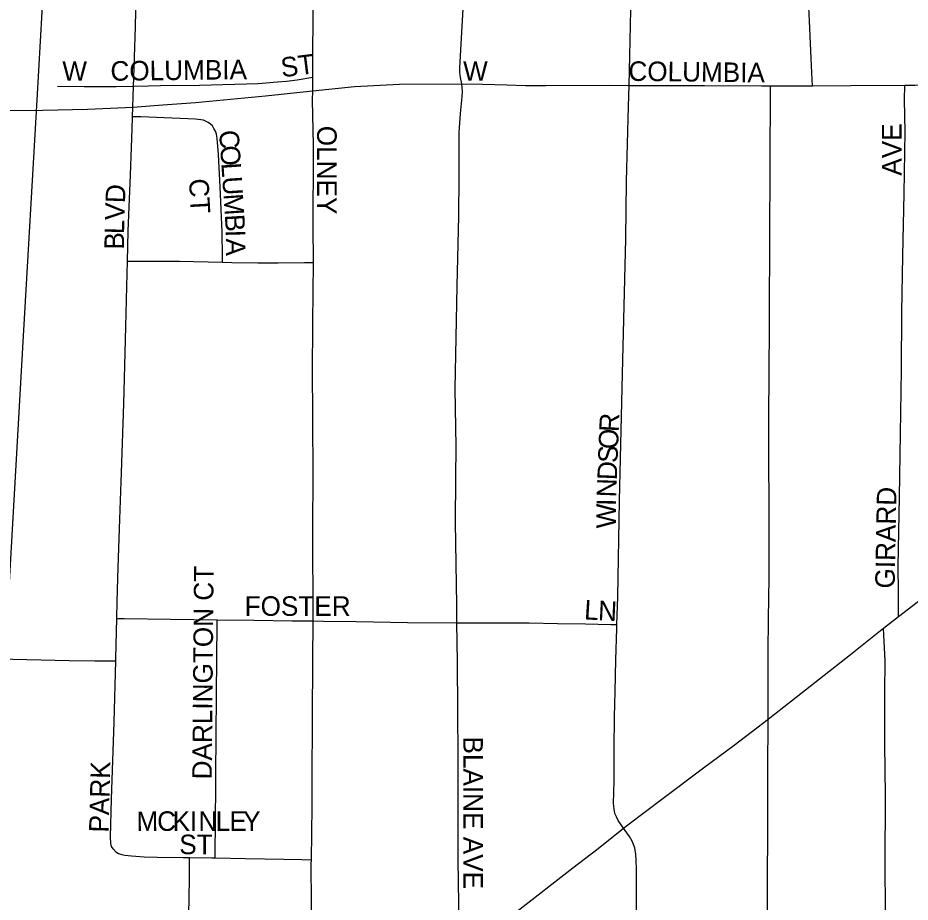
# Model space of a CAD drawing. Extents: x -97 to 34, y -21 to 22.
# Drawn here: x 5.1003 to 5.5326, y 18.9937 to 19.4221 of the extents above; entities that cross this region are included whole.
import ezdxf

# ---------------------------------------------------------------- set-up
doc = ezdxf.new("R2010")
doc.units = 0
for name, color, linetype in [('GM_X_City_Street', 7, 'Continuous'), ('GM_X_City_Street_Text', 7, 'Continuous'), ('GM_X_Rail_Line', 7, 'Continuous'), ('GM_X_State_Route', 7, 'Continuous')]:
    doc.layers.add(name, color=color, linetype=linetype)

msp = doc.modelspace()

# ---------------------------------------------------------------- linework, layer by layer
at = {"layer": 'GM_X_City_Street'}
for points in [[(5.15634, 19.38897), (5.15647, 19.39301), (5.15721, 19.41779), (5.1578, 19.44016), (5.15836, 19.45872), (5.15888, 19.47608), (5.15934, 19.49148), (5.15976, 19.50528), (5.16016, 19.52049), (5.16054, 19.53449), (5.16098, 19.55246), (5.16153, 19.56341)], [(5.24317, 19.39332), (5.24317, 19.39456), (5.24338, 19.43167), (5.24346, 19.45336), (5.24339, 19.4689), (5.24358, 19.48131), (5.24352, 19.48737), (5.24364, 19.5147), (5.24325, 19.54835), (5.24309, 19.56256)], [(5.39638, 19.38931), (5.39674, 19.40369), (5.39761, 19.44092), (5.39861, 19.48431), (5.39814, 19.52244)], [(5.48528, 19.3891), (5.48481, 19.39888), (5.48376, 19.42056), (5.48241, 19.44991)], [(5.15634, 19.38897), (5.16354, 19.38911), (5.16937, 19.38923), (5.18832, 19.38946), (5.21675, 19.39032), (5.22614, 19.39102), (5.23046, 19.3914), (5.23557, 19.39208), (5.24317, 19.39332)], [(5.24314, 19.38666), (5.24317, 19.39332)], [(5.11958, 19.38902), (5.13241, 19.38887), (5.14794, 19.38879), (5.15634, 19.38897)], [(5.1559, 19.37403), (5.15604, 19.37875), (5.15634, 19.38897)], [(5.31303, 19.12908), (5.31292, 19.13769), (5.31233, 19.17754), (5.31247, 19.19906), (5.31262, 19.21449), (5.31219, 19.24242), (5.31315, 19.29204), (5.31391, 19.32613), (5.31408, 19.34476), (5.31416, 19.36649), (5.31469, 19.37578), (5.31548, 19.3838), (5.31564, 19.38648), (5.31561, 19.38808), (5.3153, 19.39015)], [(5.3153, 19.39015), (5.32537, 19.38986), (5.33729, 19.38956), (5.34616, 19.3893), (5.35603, 19.38929), (5.38707, 19.38941), (5.39638, 19.38931)], [(5.39049, 19.12816), (5.39094, 19.1416), (5.39177, 19.1881), (5.39341, 19.25635), (5.39478, 19.31507), (5.39517, 19.3429), (5.39612, 19.37911), (5.39638, 19.38931)], [(5.39638, 19.38931), (5.40255, 19.38925), (5.41175, 19.38923), (5.42085, 19.38923), (5.43294, 19.3893), (5.4606, 19.38912), (5.46488, 19.3891)], [(5.46381, 19.0824), (5.4637, 19.09452), (5.46376, 19.11473), (5.46396, 19.13089), (5.46431, 19.15081), (5.46431, 19.1701), (5.46423, 19.18597), (5.46412, 19.20807), (5.46404, 19.22918), (5.46419, 19.24933), (5.46437, 19.27387), (5.46446, 19.28988), (5.46454, 19.30375), (5.46455, 19.3097), (5.46455, 19.31617), (5.46457, 19.32233), (5.4646, 19.32859), (5.46467, 19.33736), (5.46473, 19.34722), (5.46477, 19.35612), (5.4648, 19.36483), (5.46483, 19.3739), (5.46487, 19.38652), (5.46488, 19.3891)], [(5.46488, 19.3891), (5.48219, 19.38905), (5.48528, 19.3891)], [(5.48528, 19.3891), (5.50387, 19.38935), (5.52997, 19.38945)], [(5.52685, 19.132), (5.52685, 19.14084), (5.52686, 19.14393), (5.52676, 19.15627), (5.52733, 19.19002), (5.52785, 19.22059), (5.52829, 19.25161), (5.52853, 19.27946), (5.52905, 19.3068), (5.52965, 19.33691), (5.53022, 19.36694), (5.52989, 19.38236), (5.52997, 19.38945)], [(5.52997, 19.38945), (5.53485, 19.38947), (5.56519, 19.38978)], [(5.24349, 19.30357), (5.24353, 19.30784), (5.2434, 19.31715), (5.24344, 19.36035), (5.24311, 19.38213), (5.24314, 19.38666)], [(5.15341, 19.30413), (5.15379, 19.31868), (5.15486, 19.34604), (5.15571, 19.36813), (5.1559, 19.37403)], [(5.19945, 19.30373), (5.19942, 19.30637), (5.19929, 19.31826), (5.19835, 19.34016), (5.19755, 19.35581), (5.19692, 19.36372), (5.19656, 19.36577), (5.19612, 19.36719), (5.19531, 19.36852), (5.19451, 19.36968), (5.19362, 19.37057), (5.19256, 19.37137), (5.19123, 19.37208), (5.19016, 19.37244), (5.18891, 19.3727), (5.18642, 19.37297), (5.17887, 19.37332), (5.15993, 19.37403), (5.1559, 19.37403)], [(5.1482, 19.13115), (5.14841, 19.13944), (5.14892, 19.15582), (5.14971, 19.1793), (5.15046, 19.2018), (5.15162, 19.23505), (5.1524, 19.26605), (5.15309, 19.29198), (5.15341, 19.30413)], [(5.15341, 19.30413), (5.15616, 19.30414), (5.17857, 19.30423), (5.19945, 19.30373)], [(5.19945, 19.30373), (5.20399, 19.30361), (5.21654, 19.30335), (5.22632, 19.30345), (5.23912, 19.30353), (5.24349, 19.30357)], [(5.24328, 19.12991), (5.24331, 19.13843), (5.24317, 19.16608), (5.24328, 19.20945), (5.24312, 19.2187), (5.24312, 19.22179), (5.24312, 19.23103), (5.24307, 19.24966), (5.24321, 19.2745), (5.24349, 19.30357)], [(5.14769, 19.11062), (5.14772, 19.11183), (5.1482, 19.13115)], [(5.1482, 19.13115), (5.15178, 19.1311), (5.17428, 19.13075), (5.19686, 19.13046)], [(5.19588, 19.01513), (5.19594, 19.01988), (5.19607, 19.03008), (5.19635, 19.07657), (5.19652, 19.09207), (5.19666, 19.11376), (5.1968, 19.12663), (5.19686, 19.13046)], [(5.19686, 19.13046), (5.2146, 19.13022), (5.23324, 19.13002), (5.24328, 19.12991)], [(5.2425, 19.01428), (5.24292, 19.04007), (5.24282, 19.05243), (5.24309, 19.08323), (5.24321, 19.11079), (5.24328, 19.12991)], [(5.24328, 19.12991), (5.24834, 19.12982), (5.26428, 19.12961), (5.28913, 19.12912), (5.31303, 19.12908)], [(5.31303, 19.12908), (5.31399, 19.12905), (5.33192, 19.129), (5.34802, 19.12896), (5.36171, 19.12875), (5.37523, 19.12848), (5.3875, 19.12822), (5.39049, 19.12816)], [(5.3172, 18.96983), (5.31523, 18.97259), (5.31429, 18.97411), (5.314, 18.975), (5.31386, 18.97623), (5.31375, 18.97746), (5.31377, 18.9795), (5.31391, 18.99294), (5.31363, 19.01437), (5.31364, 19.03294), (5.31356, 19.06369), (5.31328, 19.11002), (5.31303, 19.12908)], [(5.39363, 19.02959), (5.39107, 19.03328), (5.39029, 19.03497), (5.38954, 19.03661), (5.3891, 19.03898), (5.38888, 19.0415), (5.3891, 19.05241), (5.38916, 19.06794), (5.38932, 19.08345), (5.38961, 19.09574), (5.38998, 19.11108), (5.39042, 19.12622), (5.39049, 19.12816)], [(5.51942, 18.85279), (5.51963, 18.85569), (5.52056, 18.88044), (5.52045, 18.90837), (5.52015, 18.93892), (5.52047, 18.96678), (5.52058, 18.99042), (5.5204, 19.01152), (5.5206, 19.04541), (5.5203, 19.07025), (5.52029, 19.08893), (5.52037, 19.09845), (5.52047, 19.10759), (5.52043, 19.11067), (5.5202, 19.11689), (5.52, 19.11999), (5.51957, 19.12641)], [(5.03552, 19.11181), (5.04227, 19.11172), (5.06384, 19.11161), (5.09096, 19.11149), (5.12521, 19.11073), (5.13765, 19.11067), (5.14769, 19.11062)], [(5.1477, 19.01814), (5.14641, 19.01953), (5.14572, 19.02071), (5.14533, 19.02209), (5.14521, 19.0253), (5.14567, 19.04355), (5.14696, 19.08087), (5.14769, 19.11062)], [(5.46308, 18.85354), (5.46314, 18.85819), (5.4632, 18.88041), (5.46325, 18.89909), (5.46352, 18.92224), (5.46356, 18.93777), (5.46342, 18.96572), (5.46349, 18.97815), (5.46346, 18.99369), (5.46347, 19.00917), (5.46363, 19.0233), (5.46365, 19.04047), (5.46368, 19.06195), (5.46385, 19.07747), (5.46381, 19.0824)], [(5.3998, 18.85438), (5.40003, 18.88233), (5.40021, 18.90094), (5.39994, 18.91951), (5.40003, 18.94435), (5.39999, 18.96606), (5.39999, 18.97848), (5.40006, 19.00019), (5.40003, 19.00945), (5.39983, 19.01409), (5.3997, 19.01685), (5.39926, 19.01996), (5.39796, 19.0233), (5.39656, 19.02543), (5.39363, 19.02959)], [(5.1477, 19.01814), (5.14908, 19.01726), (5.15066, 19.01676), (5.15217, 19.01646), (5.15528, 19.01607), (5.16156, 19.01566), (5.16777, 19.01546), (5.18045, 19.01531), (5.18346, 19.01528)], [(5.18049, 18.86326), (5.18049, 18.87169), (5.18048, 18.88866), (5.18084, 18.89981), (5.18117, 18.90987), (5.1816, 18.92531), (5.18205, 18.94184), (5.18254, 18.9594), (5.18286, 18.97508), (5.18311, 18.98738), (5.18342, 19.00488), (5.18346, 19.01528)], [(5.18346, 19.01528), (5.19434, 19.01515), (5.19588, 19.01513)], [(5.19588, 19.01513), (5.21064, 19.01486), (5.22909, 19.01452), (5.23787, 19.01437), (5.2425, 19.01428)], [(5.26493, 18.92974), (5.26308, 18.93184), (5.26112, 18.93432), (5.25956, 18.93659), (5.25716, 18.94066), (5.24848, 18.95728), (5.24459, 18.96576), (5.24361, 18.96869), (5.24334, 18.97006), (5.24302, 18.97172), (5.24293, 18.97367), (5.2426, 18.98101), (5.24259, 18.99342), (5.24246, 19.01207), (5.2425, 19.01428)]]:
    msp.add_lwpolyline(points, dxfattribs=at)
at = {"layer": 'GM_X_Rail_Line'}
msp.add_lwpolyline([(5.09413, 19.11167), (5.10323, 19.27071), (5.1096, 19.38232), (5.11375, 19.45353), (5.11635, 19.48913), (5.11778, 19.50862), (5.12129, 19.54435), (5.1261, 19.58489), (5.13142, 19.62582), (5.13441, 19.65726), (5.1348, 19.66862)], dxfattribs=at)
at = {"layer": 'GM_X_State_Route'}
for points in [[(5.3153, 19.39015), (5.31474, 19.39323), (5.31444, 19.39579), (5.31436, 19.39792), (5.31702, 19.44383), (5.31822, 19.46454), (5.31877, 19.48013), (5.31854, 19.49888), (5.31877, 19.50819), (5.31876, 19.52692), (5.31935, 19.54739)], [(5.17049, 19.37984), (5.18637, 19.38104), (5.22024, 19.38433), (5.24158, 19.3865), (5.24314, 19.38666), (5.26337, 19.38876), (5.28521, 19.38988), (5.3153, 19.39015)], [(5.04062, 19.37796), (5.06904, 19.3773), (5.09068, 19.37715), (5.11233, 19.37738), (5.13397, 19.37788), (5.15248, 19.3787), (5.15604, 19.37875), (5.17049, 19.37984)], [(5.34224, 18.98932), (5.36921, 19.01034), (5.38142, 19.01972), (5.39363, 19.02959), (5.39586, 19.03108), (5.41287, 19.04408), (5.43238, 19.05875), (5.44726, 19.06978), (5.46381, 19.0824), (5.46456, 19.08294), (5.50364, 19.11364), (5.5182, 19.12536), (5.51957, 19.12641), (5.52685, 19.132), (5.53798, 19.14055)]]:
    msp.add_lwpolyline(points, dxfattribs=at)

# ---------------------------------------------------------------- texts
at = {"layer": 'GM_X_City_Street_Text'}
for s, height, rotation, p in [('W', 0.00947, 0, (5.12183, 19.39156)), ('COLUMBIA', 0.00947, 0.683, (5.14519, 19.39156)), ('ST', 0.00947, 7.1217, (5.22827, 19.39322)), ('W', 0.00947, 0, (5.31599, 19.39156)), ('COLUMBIA', 0.00947, 359.3152, (5.39601, 19.39156)), ('AVE', 0.00947, 90, (5.52838, 19.34561)), ('C', 0.00947, 273.8642, (5.19777, 19.3674)), ('OLNEY', 0.00947, 270, (5.24528, 19.36978)), ('O', 0.00947, 273.849, (5.19828, 19.35992)), ('L', 0.00947, 273.8804, (5.19884, 19.3516)), ('U', 0.00947, 273.849, (5.19929, 19.34495)), ('D', 0.00947, 87.9671, (5.15219, 19.33218)), ('CT', 0.00947, 273.1778, (5.18317, 19.34398)), ('M', 0.00947, 273.8685, (5.19985, 19.33663)), ('V', 0.00947, 87.9889, (5.15189, 19.32386)), ('L', 0.00947, 88.6887, (5.15174, 19.31722)), ('B', 0.00947, 273.4506, (5.20052, 19.32667)), ('I', 0.00947, 271.6616, (5.20097, 19.31926)), ('B', 0.00947, 89.7814, (5.15172, 19.30977)), ('A', 0.00947, 270.153, (5.20109, 19.31516)), ('R', 0.00947, 87.7125, (5.39137, 19.22132)), ('O', 0.00947, 87.7073, (5.39104, 19.21299)), ('S', 0.00947, 87.7039, (5.39077, 19.20633)), ('D', 0.00947, 87.7041, (5.39044, 19.198)), ('N', 0.00947, 87.9452, (5.39014, 19.18969)), ('GIRARD', 0.00947, 88.9421, (5.52505, 19.14556)), ('W', 0.00947, 89.8991, (5.39004, 19.17477)), ('I', 0.00947, 88.9067, (5.39006, 19.18556)), ('DARLINGTON CT', 0.0094697, 89.4865, (5.19421, 19.05314)), ('FOSTER', 0.00947, 0, (5.21016, 19.13239)), ('L', 0.00947, 356.5276, (5.37444, 19.13072)), ('N', 0.00947, 357.2036, (5.38121, 19.13031)), ('BLAINE AVE', 0.00947, 270, (5.31611, 19.07395)), ('PARK', 0.00947, 88.4526, (5.14421, 19.02733)), ('M', 0.00947, 0.6738, (5.15781, 19.02811)), ('C', 0.00947, 0, (5.16778, 19.02823)), ('K', 0.00947, 0, (5.17528, 19.02823)), ('I', 0.00947, 0, (5.18361, 19.02823)), ('N', 0.00947, 0, (5.18778, 19.02823)), ('L', 0.00947, 0, (5.19611, 19.02823)), ('E', 0.00947, 0, (5.20278, 19.02823)), ('Y', 0.00947, 0, (5.20944, 19.02823)), ('ST', 0.00947, 0, (5.17849, 19.01694))]:
    msp.add_text(s, height=height, rotation=rotation, dxfattribs=at).set_placement(p)

doc.saveas('drawing.dxf')
